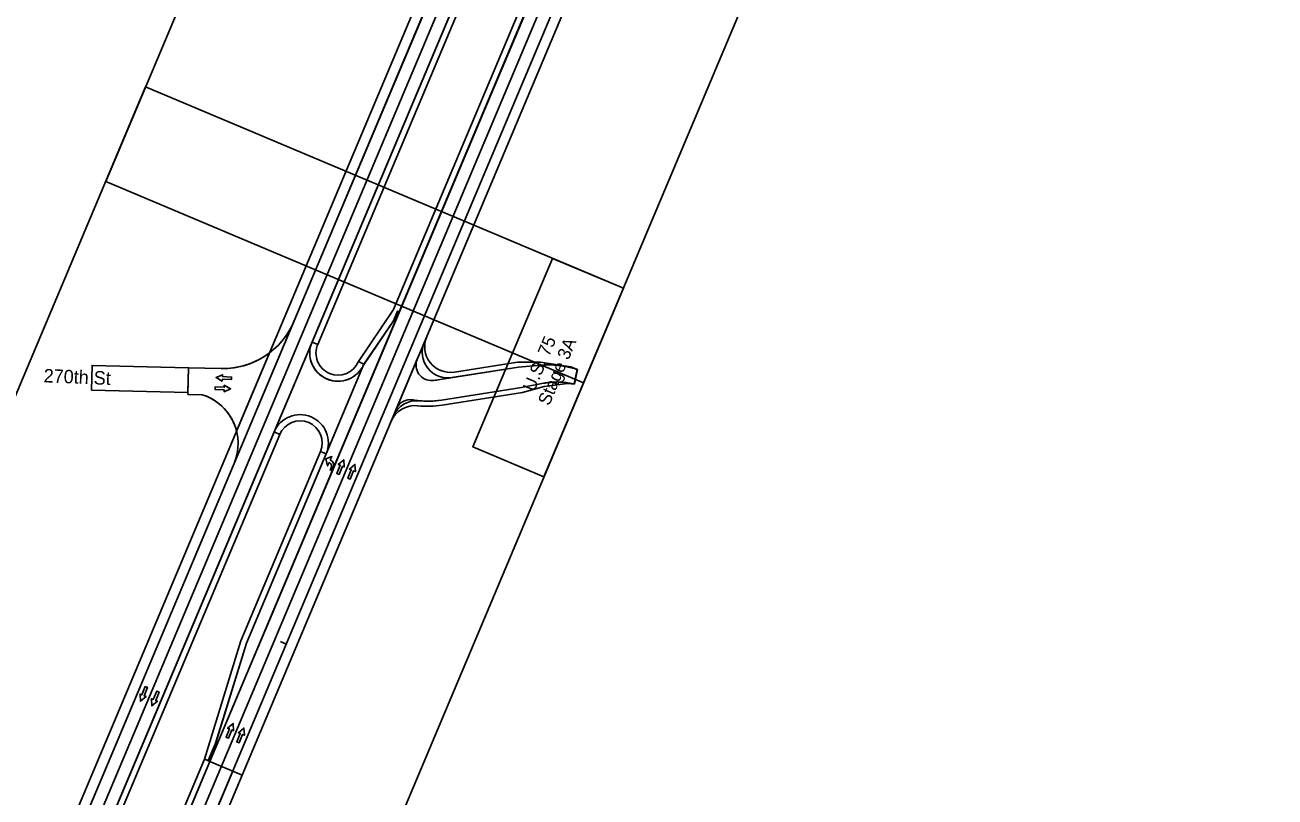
# Model space of a CAD drawing. Extents: x 14104283 to 14120882, y 8635219 to 8671666.
# Drawn here: x 14111141 to 14112358, y 8650334 to 8651086 of the extents above; entities that cross this region are included whole.
import ezdxf

# ---------------------------------------------------------------- set-up
doc = ezdxf.new("R2010")
doc.units = 0
for name, color, linetype in [('Cell', 7, 'Continuous'), ('dsnNonPlotable', 7, 'Continuous'), ('dsnPaintExistingEdgeLineRightWhite', 7, 'Continuous'), ('dsnPaintExistingLaneLineWhite', 7, 'Continuous'), ('dsnPaintPlaceBrokenLineWhite', 7, 'Continuous'), ('dsnPaintPlaceEdgeLineLeftYellow', 7, 'Continuous'), ('dsnPaintPlaceEdgeLineRightWhite', 7, 'Continuous'), ('dsnPaintRemoveDoubleCenterLineYellow', 7, 'Continuous'), ('dsnShadingGranular', 7, 'Continuous'), ('dsnShadingPaved', 7, 'Continuous'), ('dsnStgShadingPrevPav', 7, 'Continuous'), ('dsnTextFinalPlan', 7, 'Continuous'), ('dsnTextOverlapEven', 7, 'Continuous'), ('TextAlignmentLrg', 7, 'Continuous')]:
    doc.layers.add(name, color=color, linetype=linetype)

msp = doc.modelspace()

# ---------------------------------------------------------------- linework, layer by layer
at = {"layer": 'Cell'}
for p, q in [((14111437.4, 8650659.6), (14111437.1, 8650659.8)), ((14111438.2, 8650662.2), (14111438.4, 8650662.1))]:
    msp.add_line(p, q, dxfattribs=at)
for points in [[(14111342.1, 8650742.9), (14111342, 8650740.4), (14111333.2, 8650740.8), (14111333.1, 8650738.9), (14111327, 8650742.3), (14111333.4, 8650745.1), (14111333.3, 8650743.3)], [(14111326.1, 8650730.9), (14111326.2, 8650733.4), (14111335, 8650733), (14111335, 8650734.9), (14111341.2, 8650731.5), (14111334.8, 8650728.6), (14111334.9, 8650730.5)], [(14111446.9, 8650648), (14111444.5, 8650649), (14111447.9, 8650657.1), (14111446.1, 8650657.8), (14111451.4, 8650662.4), (14111451.9, 8650655.4), (14111450.2, 8650656.1)], [(14111457.7, 8650643.5), (14111455.4, 8650644.4), (14111458.7, 8650652.5), (14111456.9, 8650653.2), (14111462.2, 8650657.8), (14111462.7, 8650650.9), (14111461, 8650651.6)], [(14111258.1, 8650441.5), (14111260.4, 8650440.5), (14111257.1, 8650432.4), (14111258.8, 8650431.7), (14111253.5, 8650427.1), (14111253, 8650434.1), (14111254.7, 8650433.4)], [(14111269.2, 8650437), (14111271.5, 8650436), (14111268.2, 8650427.9), (14111269.9, 8650427.2), (14111264.6, 8650422.6), (14111264.1, 8650429.6), (14111265.8, 8650428.9)], [(14111339, 8650391.1), (14111336.7, 8650392.1), (14111340.1, 8650400.2), (14111338.3, 8650400.9), (14111343.6, 8650405.5), (14111344.1, 8650398.5), (14111342.4, 8650399.2)], [(14111349.6, 8650386.7), (14111347.2, 8650387.7), (14111350.6, 8650395.8), (14111348.8, 8650396.5), (14111354.1, 8650401.1), (14111354.6, 8650394.1), (14111352.9, 8650394.8)]]:
    msp.add_lwpolyline(points, close=True, dxfattribs=at)
for points in [[(14111333.3, 8650743.3), (14111333.4, 8650745.1), (14111327, 8650742.3), (14111333.1, 8650738.9), (14111333.2, 8650740.8), (14111342, 8650740.4), (14111342.1, 8650742.9), (14111333.3, 8650743.3)], [(14111334.9, 8650730.5), (14111334.8, 8650728.6), (14111341.2, 8650731.5), (14111335, 8650734.9), (14111335, 8650733), (14111326.2, 8650733.4), (14111326.1, 8650730.9), (14111334.9, 8650730.5)], [(14111434, 8650663.3), (14111439.8, 8650665.5), (14111438.2, 8650662.2)], [(14111434, 8650663.3), (14111439.8, 8650665.5), (14111438.2, 8650662.2)], [(14111437.1, 8650659.8), (14111435.6, 8650656.4), (14111434, 8650663.3)], [(14111437.1, 8650659.8), (14111435.6, 8650656.4), (14111434, 8650663.3)], [(14111437.4, 8650659.6), (14111437.1, 8650659.8)], [(14111438.2, 8650662.2), (14111438.4, 8650662.1)], [(14111441, 8650655.3), (14111439.7, 8650651.9), (14111438.3, 8650652.5), (14111439.3, 8650654.9)], [(14111441, 8650655.3), (14111439.7, 8650651.9), (14111438.3, 8650652.5), (14111439.3, 8650654.9)], [(14111450.2, 8650656.1), (14111451.9, 8650655.4), (14111451.4, 8650662.4), (14111446.1, 8650657.8), (14111447.9, 8650657.1), (14111444.5, 8650649), (14111446.9, 8650648), (14111450.2, 8650656.1)], [(14111461, 8650651.6), (14111462.7, 8650650.9), (14111462.2, 8650657.8), (14111456.9, 8650653.2), (14111458.7, 8650652.5), (14111455.4, 8650644.4), (14111457.7, 8650643.5), (14111461, 8650651.6)], [(14111254.7, 8650433.4), (14111253, 8650434.1), (14111253.5, 8650427.1), (14111258.8, 8650431.7), (14111257.1, 8650432.4), (14111260.4, 8650440.5), (14111258.1, 8650441.5), (14111254.7, 8650433.4)], [(14111265.8, 8650428.9), (14111264.1, 8650429.6), (14111264.6, 8650422.6), (14111269.9, 8650427.2), (14111268.2, 8650427.9), (14111271.5, 8650436), (14111269.2, 8650437), (14111265.8, 8650428.9)], [(14111342.4, 8650399.2), (14111344.1, 8650398.5), (14111343.6, 8650405.5), (14111338.3, 8650400.9), (14111340.1, 8650400.2), (14111336.7, 8650392.1), (14111339, 8650391.1), (14111342.4, 8650399.2)], [(14111352.9, 8650394.8), (14111354.6, 8650394.1), (14111354.1, 8650401.1), (14111348.8, 8650396.5), (14111350.6, 8650395.8), (14111347.2, 8650387.7), (14111349.6, 8650386.7), (14111352.9, 8650394.8)]]:
    msp.add_lwpolyline(points, dxfattribs=at)
for centre, major_axis in [((14111436, 8650656.2), (-1.38, -3.41)), ((14111436, 8650656.2), (-1.38, -3.41)), ((14111436.4, 8650657.2), (-1.97, -4.87)), ((14111436.4, 8650657.2), (-1.97, -4.87))]:
    msp.add_ellipse(centre, major_axis=major_axis, ratio=0.9474, start_param=1.570796, end_param=3.141593, dxfattribs=at)
at = {"layer": 'dsnNonPlotable'}
for points in [[(14111219.5, 8650933.3), (14111828.1, 8652377.8), (14112293.5, 8652181.8), (14111684.9, 8650737.2)], [(14110649.8, 8649580.9), (14111258.3, 8651025.5), (14111723.7, 8650829.4), (14111115.1, 8649384.9)]]:
    msp.add_lwpolyline(points, close=True, dxfattribs=at)
at = {"layer": 'dsnPaintExistingEdgeLineRightWhite'}
msp.add_line((14110924.4, 8649364.5), (14118862.5, 8668214.7), dxfattribs=at)
at = {"layer": 'dsnPaintExistingLaneLineWhite'}
msp.add_line((14111367.7, 8650479.1), (14111445.3, 8650663.4), dxfattribs=at)
at = {"layer": 'dsnPaintPlaceBrokenLineWhite'}
for p, q in [((14110829.5, 8649404.5), (14118424.3, 8667439.6)), ((14110913.3, 8649369.2), (14114932.5, 8658913.4))]:
    msp.add_line(p, q, dxfattribs=at)
at = {"layer": 'dsnPaintPlaceEdgeLineLeftYellow'}
for p, q in [((14113594.8, 8655940.3), (14111420.5, 8650777)), ((14111505.3, 8650805.9), (14113533.3, 8655621.7)), ((14111470.9, 8650755.1), (14111505.3, 8650805.9)), ((14111356.7, 8650483.8), (14111434.3, 8650668.1)), ((14111321.1, 8650368.5), (14111356.7, 8650483.8)), ((14110902.3, 8649373.8), (14111321.1, 8650368.5))]:
    msp.add_line(p, q, dxfattribs=at)
msp.add_lwpolyline([(14111383.6, 8650689.4), (14110840.5, 8649399.8), (14109233.5, 8645585.3)], dxfattribs=at)
for centre, start, end in [((14111445.8, 8650766.3), 157.1633, 335.8501), ((14111408.9, 8650678.8), 67.1633, 156.8935), ((14111408.9, 8650678.8), 337.1465, 67.1633)]:
    msp.add_arc(centre, 27.5, start, end, dxfattribs=at)
at = {"layer": 'dsnPaintPlaceEdgeLineRightWhite'}
msp.add_line((14113555.5, 8655908.7), (14111402.9, 8650797.1), dxfattribs=at)
msp.add_lwpolyline([(14111344.6, 8650658.6), (14110818.4, 8649409.2), (14109217, 8645608.1)], dxfattribs=at)
at = {"layer": 'dsnPaintRemoveDoubleCenterLineYellow'}
msp.add_line((14110913.3, 8649369.2), (14114932.5, 8658913.4), dxfattribs=at)
at = {"layer": 'dsnShadingGranular'}
msp.add_line((14111523, 8650760.3), (14111502.5, 8650711.7), dxfattribs=at)
at = {"layer": 'dsnShadingPaved'}
for p, q in [((14113555.5, 8655612.4), (14110924.4, 8649364.5)), ((14111505.5, 8650806.3), (14113533.3, 8655621.7)), ((14111321.1, 8650368.5), (14111505.5, 8650806.3)), ((14111505.3, 8650805.7), (14111321.1, 8650368.5)), ((14111470.6, 8650754.6), (14111505.3, 8650805.7)), ((14111402.9, 8650797.1), (14111344.6, 8650658.6)), ((14111383.6, 8650689.4), (14111420.5, 8650777)), ((14111299.6, 8650726), (14111300.2, 8650752)), ((14111300.2, 8650752), (14111332, 8650751.3)), ((14111313.6, 8650725.7), (14111299.6, 8650726)), ((14111356.7, 8650483.8), (14111434.3, 8650668.1)), ((14111321.1, 8650368.5), (14111356.7, 8650483.8)), ((14110902.3, 8649373.8), (14111321.1, 8650368.5))]:
    msp.add_line(p, q, dxfattribs=at)
for points in [[(14118413.2, 8667444.3), (14110818.4, 8649409.2), (14109142.6, 8645431.4)], [(14109164.7, 8645422.1), (14110840.5, 8649399.8), (14118435.4, 8667434.9)]]:
    msp.add_lwpolyline(points, dxfattribs=at)
for centre, radius, start, end in [((14111333.8, 8650826.2), 75, 268.6633, 337.1633), ((14111445.8, 8650766.3), 27.5, 157.1801, 247.1633), ((14111445.8, 8650766.3), 27.5, 247.1633, 335.8501), ((14111298.5, 8650678), 50, 337.1633, 72.4031), ((14111408.9, 8650678.8), 27.5, 67.1633, 156.8935), ((14111408.9, 8650678.8), 27.5, 337.1465, 67.1633)]:
    msp.add_arc(centre, radius, start, end, dxfattribs=at)
at = {"layer": 'dsnStgShadingPrevPav'}
for p, q in [((14110809.2, 8649413), (14118404, 8667448.1)), ((14118413.2, 8667444.3), (14110818.4, 8649409.2)), ((14113594.8, 8655940.3), (14111420.5, 8650777)), ((14111402.9, 8650797.1), (14113555.5, 8655908.7)), ((14113533.3, 8655621.7), (14111505.5, 8650806.3)), ((14111352.5, 8650355.3), (14113564.7, 8655608.5)), ((14111505.5, 8650806.3), (14111321.1, 8650368.5)), ((14111344.6, 8650658.6), (14111402.9, 8650797.1)), ((14111383.6, 8650689.4), (14111420.5, 8650777)), ((14111420.5, 8650777), (14111383.6, 8650689.4)), ((14111420.5, 8650777), (14111426, 8650774.7)), ((14111532.2, 8650782.1), (14111529.9, 8650776.7)), ((14111379.2, 8650766.5), (14111347, 8650690.1)), ((14111529.9, 8650776.7), (14111523, 8650760.3)), ((14111471.1, 8650755.6), (14111434.3, 8650668.1)), ((14111465.6, 8650758), (14111471.1, 8650755.6)), ((14111523, 8650760.3), (14111502.5, 8650711.7)), ((14111620.7, 8650757.3), (14111559.1, 8650747.7)), ((14111642.9, 8650757.4), (14111620.7, 8650757.3)), ((14111643.4, 8650754.4), (14111621.5, 8650752.4)), ((14111621.5, 8650752.4), (14111643.4, 8650754.4)), ((14111299.6, 8650726), (14111300.2, 8650752)), ((14111300.2, 8650752), (14111332, 8650751.3)), ((14111621.5, 8650752.4), (14111543.5, 8650740.2)), ((14111543.5, 8650740.2), (14111556.8, 8650742.3)), ((14111556.8, 8650742.3), (14111621.5, 8650752.4)), ((14111678.8, 8650750.4), (14111672.4, 8650752.1)), ((14111672.4, 8650752.1), (14111678.8, 8650750.4)), ((14111675.9, 8650736.2), (14111678.8, 8650750.4)), ((14111677.5, 8650744), (14111675.9, 8650736.2)), ((14111676.2, 8650736.1), (14111677.8, 8650744)), ((14111678.8, 8650750.4), (14111677.5, 8650744)), ((14111677.8, 8650744), (14111677.5, 8650744)), ((14111677.5, 8650744), (14111677.8, 8650744)), ((14111677.8, 8650744), (14111679, 8650750.3)), ((14111546.6, 8650720.4), (14111624.6, 8650732.6)), ((14111624.6, 8650732.6), (14111546.6, 8650720.4)), ((14111624.6, 8650732.6), (14111646.1, 8650736.8)), ((14111646.1, 8650736.8), (14111624.6, 8650732.6)), ((14111625.4, 8650727.7), (14111646.6, 8650733.8)), ((14111669.4, 8650737.2), (14111675.9, 8650736.2)), ((14111675.9, 8650736.2), (14111669.4, 8650737.2)), ((14111313.6, 8650725.7), (14111299.6, 8650726)), ((14111547.4, 8650715.5), (14111625.4, 8650727.7)), ((14111499.6, 8650704.6), (14111497.5, 8650699.8)), ((14111502.5, 8650711.7), (14111499.6, 8650704.6)), ((14111389.1, 8650687.1), (14111383.6, 8650689.4)), ((14111434.3, 8650668.1), (14111428.7, 8650670.4)), ((14111321.1, 8650368.5), (14111352.5, 8650355.3))]:
    msp.add_line(p, q, dxfattribs=at)
for points in [[(14113600.3, 8655938), (14111426, 8650774.7), (14111420.5, 8650777), (14113594.8, 8655940.3)], [(14111465.6, 8650758), (14111500, 8650808.6), (14113527.8, 8655624.1), (14113533.3, 8655621.7), (14111505.5, 8650806.3), (14111503.6, 8650807.1), (14111499.8, 8650797.8), (14111471.1, 8650755.6)], [(14111321.1, 8650368.5), (14111319.3, 8650369.3), (14111327.1, 8650387.7), (14111356.7, 8650483.8), (14111471.1, 8650755.6), (14111499.8, 8650797.8), (14111503.6, 8650807.1), (14111505.5, 8650806.3)], [(14111299.6, 8650728), (14111205.7, 8650730.2), (14111206.3, 8650754.2), (14111300.2, 8650752)], [(14109239, 8645583), (14111389.1, 8650687.1), (14111383.6, 8650689.4), (14109233.5, 8645585.3)], [(14111315.6, 8650370.9), (14111351.1, 8650486.1), (14111428.7, 8650670.4), (14111434.3, 8650668.1), (14111356.7, 8650483.8), (14111327.1, 8650387.7), (14111319.3, 8650369.3)], [(14110622.7, 8648725.7), (14111315.6, 8650370.9), (14111321.1, 8650368.5), (14110628.3, 8648723.4)], [(14110902.3, 8649373.8), (14110924.4, 8649364.5), (14111343.3, 8650359.2), (14111321.1, 8650368.5)], [(14110933.6, 8649360.6), (14111352.5, 8650355.3), (14111343.3, 8650359.2), (14110924.4, 8649364.5)]]:
    msp.add_lwpolyline(points, close=True, dxfattribs=at)
for points in [[(14111679, 8650750.3), (14111672.5, 8650752.7), (14111642.9, 8650757.4)], [(14111646.6, 8650733.8), (14111669.3, 8650736.6), (14111676.2, 8650736.1)], [(14111383.6, 8650689.4), (14110840.5, 8649399.8), (14109233.5, 8645585.3)], [(14109217, 8645608.1), (14110818.4, 8649409.2), (14111344.6, 8650658.6)]]:
    msp.add_lwpolyline(points, dxfattribs=at)
for centre, radius, start, end in [((14111555.2, 8650772.4), 25, 157.1633, 278.89), ((14111333.8, 8650826.2), 75, 268.6633, 307.2369), ((14111445.8, 8650766.3), 21.5, 157.1633, 247.1633), ((14111552.9, 8650767), 25, 157.1633, 278.89), ((14111552.9, 8650767), 25, 157.1633, 278.89), ((14111445.8, 8650766.3), 21.5, 247.1633, 337.1633), ((14111536.8, 8650754.5), 15, 157.1633, 273.9019), ((14111536.8, 8650754.5), 15, 157.1633, 273.9019), ((14111533.4, 8650804.4), 65, 273.9019, 278.89), ((14111533.4, 8650804.4), 65, 273.9019, 278.89), ((14111298.5, 8650678), 50, 14.0332, 72.4031), ((14111522.6, 8650694.9), 25, 84.3469, 157.1633), ((14111522.6, 8650694.9), 25, 84.3469, 157.1633), ((14111516.4, 8650705.9), 15, 80.1639, 157.1633), ((14111516.4, 8650705.9), 15, 80.1639, 157.1633), ((14111533.4, 8650804.4), 85, 260.1639, 278.89), ((14111533.4, 8650804.4), 85, 260.1639, 264.3457), ((14111533.4, 8650804.4), 85, 264.3457, 278.89), ((14111520.6, 8650690.1), 25, 83.5772, 157.1633), ((14111533.4, 8650804.4), 90, 263.5772, 278.89), ((14111408.9, 8650678.8), 21.5, 67.1633, 157.1633), ((14111408.9, 8650678.8), 21.5, 337.1633, 67.1633)]:
    msp.add_arc(centre, radius, start, end, dxfattribs=at)
for points in [[(14111672.4, 8650752.1), (14111671.9, 8650752.2), (14111671, 8650752.5), (14111669.6, 8650752.8), (14111668.2, 8650753.1), (14111666.7, 8650753.4), (14111665.3, 8650753.6), (14111663.9, 8650753.9), (14111662.4, 8650754.1), (14111661, 8650754.2), (14111659.5, 8650754.4), (14111658.1, 8650754.5), (14111656.6, 8650754.6), (14111655.1, 8650754.7), (14111653.7, 8650754.8), (14111652.2, 8650754.8), (14111650.7, 8650754.8), (14111649.3, 8650754.8), (14111647.8, 8650754.7), (14111646.3, 8650754.6), (14111644.8, 8650754.5), (14111643.9, 8650754.4), (14111643.4, 8650754.4)], [(14111643.4, 8650754.4), (14111643.9, 8650754.4), (14111644.8, 8650754.5), (14111646.3, 8650754.6), (14111647.8, 8650754.7), (14111649.3, 8650754.8), (14111650.7, 8650754.8), (14111652.2, 8650754.8), (14111653.7, 8650754.8), (14111655.1, 8650754.7), (14111656.6, 8650754.6), (14111658.1, 8650754.5), (14111659.5, 8650754.4), (14111661, 8650754.2), (14111662.4, 8650754.1), (14111663.9, 8650753.9), (14111665.3, 8650753.6), (14111666.7, 8650753.4), (14111668.2, 8650753.1), (14111669.6, 8650752.8), (14111671, 8650752.5), (14111671.9, 8650752.2), (14111672.4, 8650752.1)], [(14111646.1, 8650736.8), (14111646.5, 8650736.9), (14111647.3, 8650737), (14111648.4, 8650737.2), (14111649.6, 8650737.4), (14111650.7, 8650737.5), (14111651.9, 8650737.7), (14111653, 8650737.8), (14111654.2, 8650737.9), (14111655.4, 8650738), (14111656.5, 8650738), (14111657.7, 8650738), (14111658.9, 8650738.1), (14111660.1, 8650738.1), (14111661.2, 8650738), (14111662.4, 8650738), (14111663.6, 8650737.9), (14111664.7, 8650737.8), (14111665.9, 8650737.7), (14111667.1, 8650737.6), (14111668.2, 8650737.4), (14111669, 8650737.3), (14111669.4, 8650737.2)], [(14111669.4, 8650737.2), (14111669, 8650737.3), (14111668.2, 8650737.4), (14111667.1, 8650737.6), (14111665.9, 8650737.7), (14111664.7, 8650737.8), (14111663.6, 8650737.9), (14111662.4, 8650738), (14111661.2, 8650738), (14111660.1, 8650738.1), (14111658.9, 8650738.1), (14111657.7, 8650738), (14111656.5, 8650738), (14111655.4, 8650738), (14111654.2, 8650737.9), (14111653, 8650737.8), (14111651.9, 8650737.7), (14111650.7, 8650737.5), (14111649.6, 8650737.4), (14111648.4, 8650737.2), (14111647.3, 8650737), (14111646.5, 8650736.9), (14111646.1, 8650736.8)]]:
    msp.add_open_spline(points, degree=3, dxfattribs=at)
at = {"layer": 'dsnTextOverlapEven'}
for points in [[(14111723.7, 8650829.4), (14111646.3, 8650645.7), (14111577.2, 8650674.9), (14111654.6, 8650858.5)], [(14111577.2, 8650674.9), (14111654.6, 8650858.5), (14111723.7, 8650829.4), (14111646.3, 8650645.7)]]:
    msp.add_lwpolyline(points, close=True, dxfattribs=at)
at = {"layer": 'TextAlignmentLrg'}
msp.add_line((14111394.8, 8650483), (14111389.7, 8650485.2), dxfattribs=at)

# ---------------------------------------------------------------- texts
at = {"layer": 'dsnTextFinalPlan'}
msp.add_text('270th St', height=13.12, rotation=357.6374, dxfattribs=at).set_placement((14111158.9, 8650737.8))
at = {"layer": 'dsnTextOverlapEven'}
for s, p in [('U.S. 75', (14111636.9, 8650727.9)), ('Stage 3A', (14111651.5, 8650714.3))]:
    msp.add_text(s, height=12.5, rotation=67.1547, dxfattribs=at).set_placement(p)

doc.saveas('drawing.dxf')
